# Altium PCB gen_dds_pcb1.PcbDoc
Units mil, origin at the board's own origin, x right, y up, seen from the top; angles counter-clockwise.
Board outline 6000 x 4000 mil, 2 copper layers (Top Layer, Bottom Layer); 23 components, 25 nets, 105 pads, 7 vias.
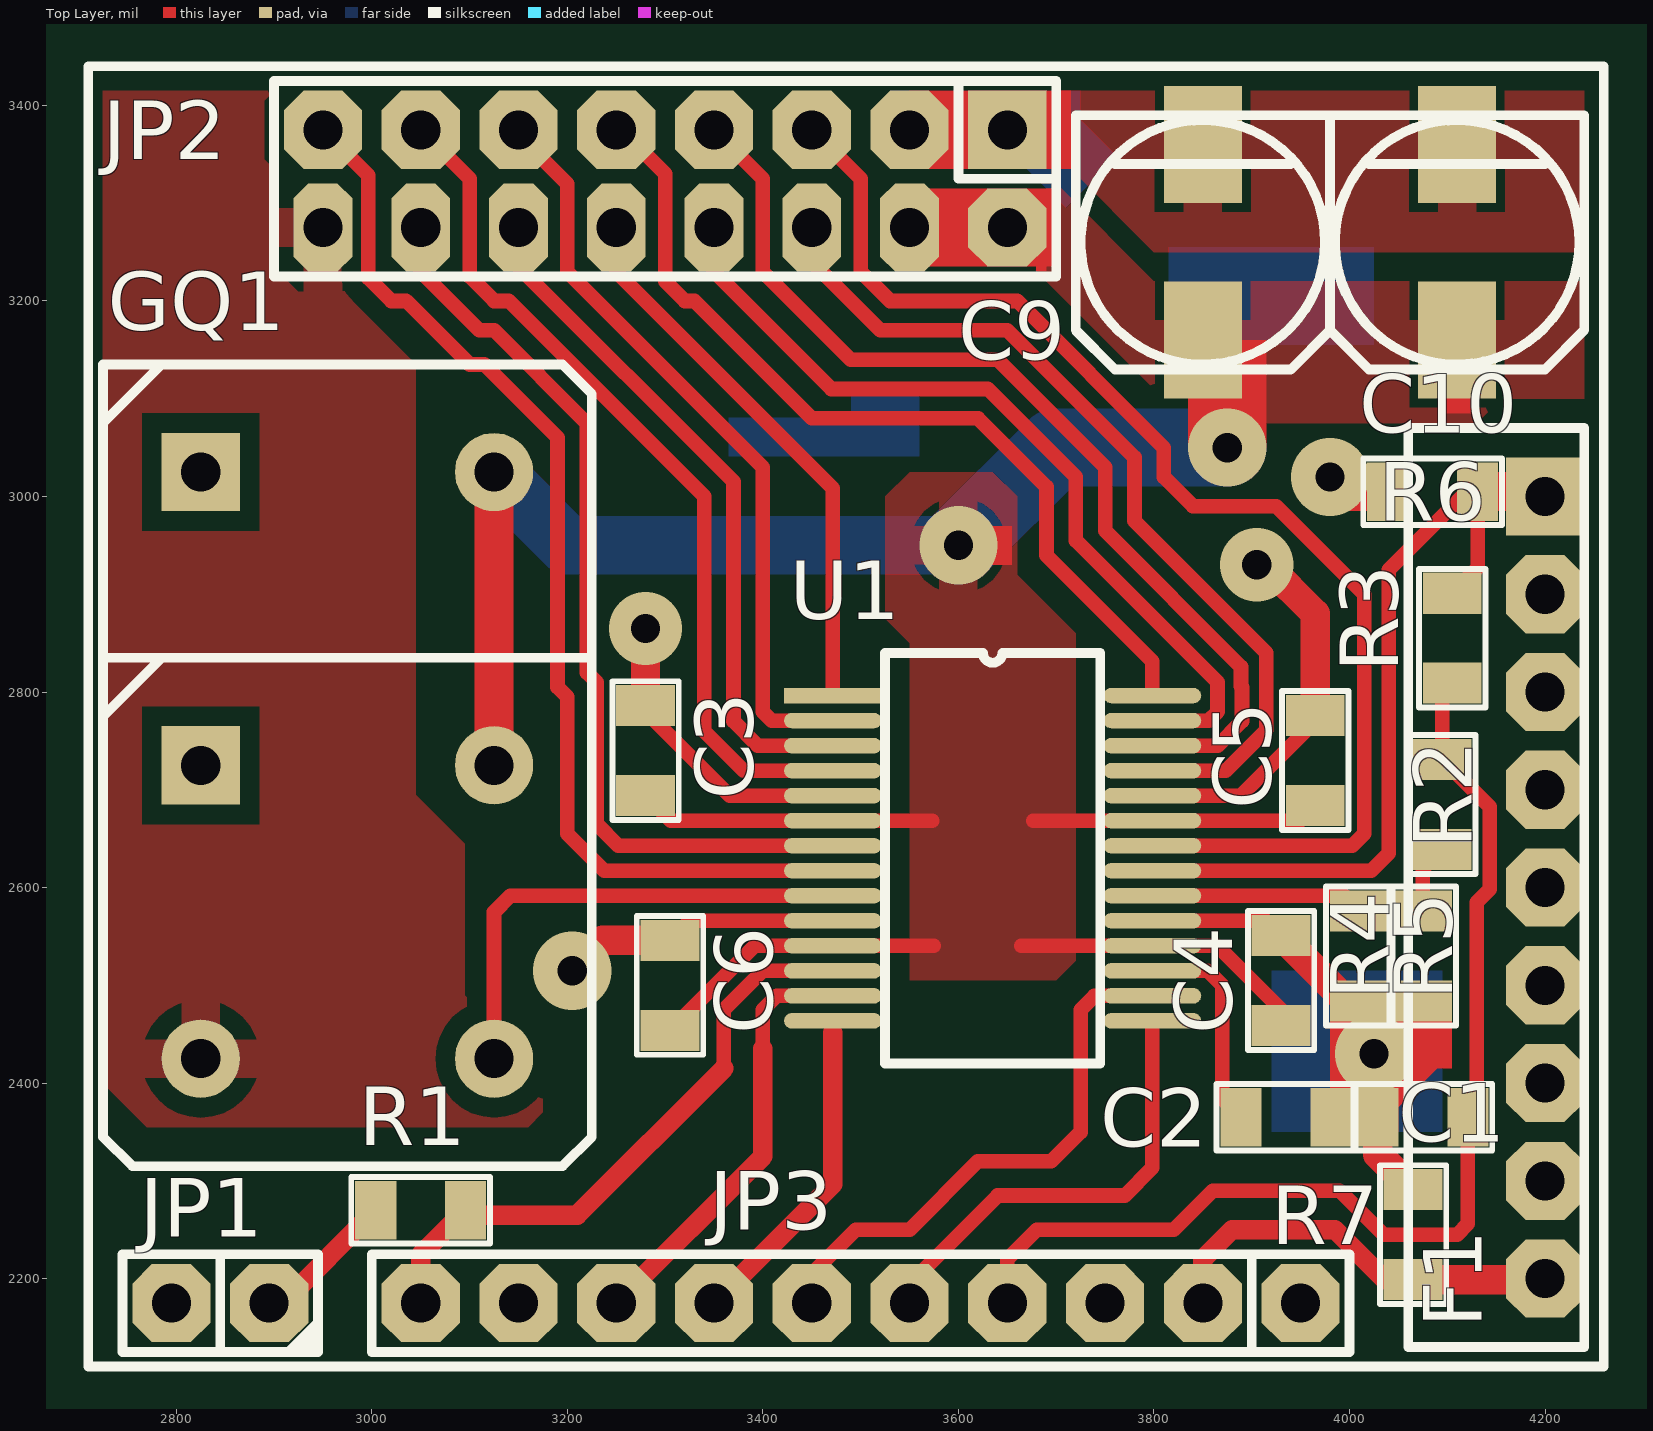
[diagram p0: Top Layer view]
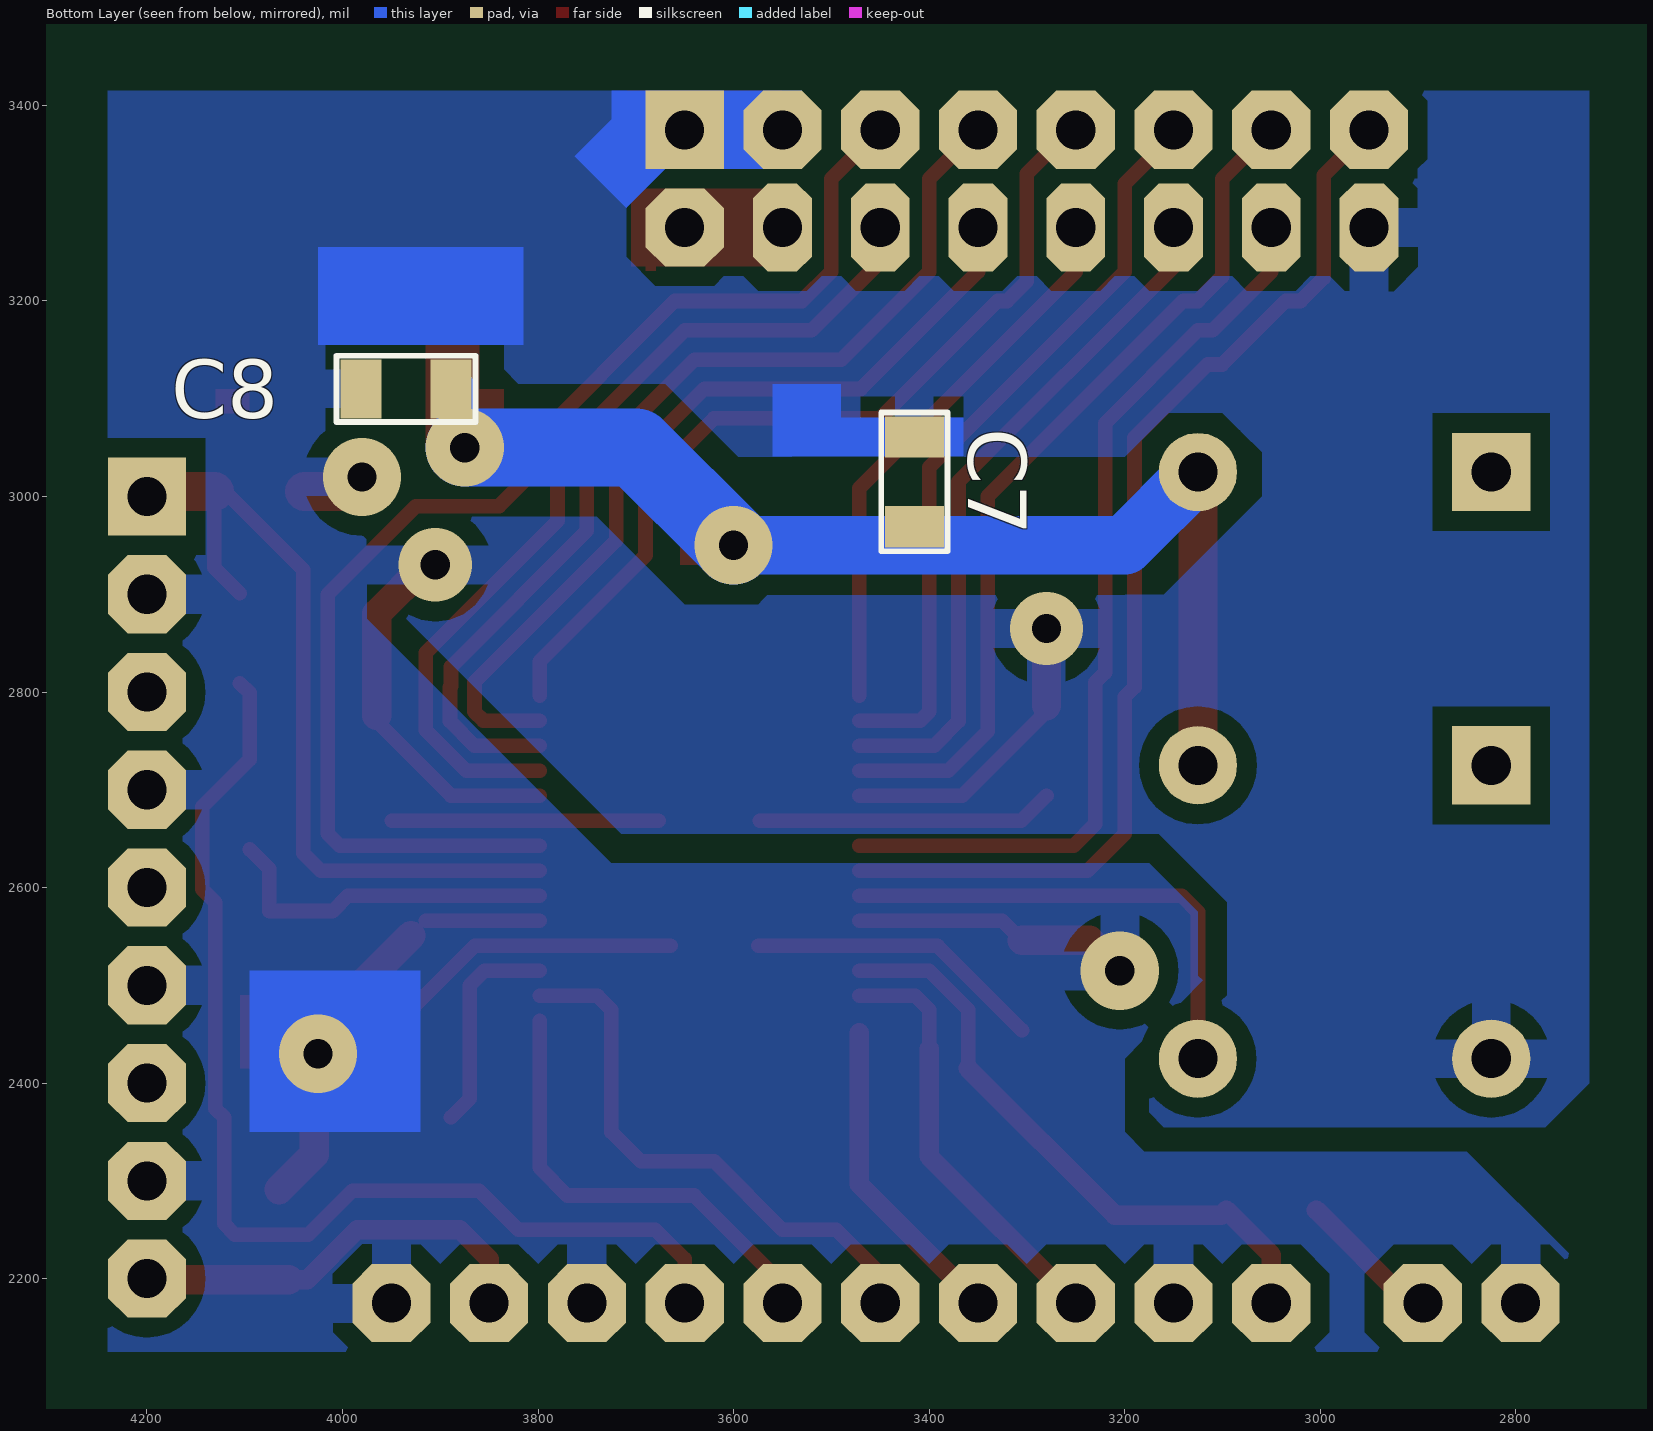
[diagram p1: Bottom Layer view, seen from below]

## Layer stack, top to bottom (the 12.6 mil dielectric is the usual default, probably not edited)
Top Layer: signal copper 1.4
Dielectric: dielectric 12.6, FR-4, Dk 4.8
Bottom Layer: signal copper 1.4

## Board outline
1000,1000 7000,1000 7000,5000 1000,5000

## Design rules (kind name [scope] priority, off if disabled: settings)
Clearance [All] p1: gap=20
PlaneConnect [All] p1: planeconnectstyle=Relief reliefexpansion=20 reliefentries=4 reliefconductorwidth=40 reliefairgap=20
PolygonConnect [All] p1: connectstyle=Relief reliefconductorwidth=40 reliefentries=4 polygonreliefangle="90 Angle"
RoutingVias [All] p1: holewidth=28 width=50 viastyle="Through Hole" minholewidth=28 minwidth=50 maxholewidth=28 maxwidth=50
SilkscreenOverComponentPads [All] p1: minsilkscreentomaskgap=10
SolderMaskExpansion [All] p1: expansion=4
Width [All] p1: maxlimit=80 minlimit=10 preferedwidth=20 minimp=50.000000 maximp=50.000000 favimp=50.000000
26 further rules are at their usual default settings.

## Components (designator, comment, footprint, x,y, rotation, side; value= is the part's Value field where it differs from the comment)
C1 "2,2n" 0805 4075,2365 r180 top
C2 "100n" 0805 3935,2365 r0 top
C3 "100n" 0805 3280,2740 r90 top
C4 "100n" 0805 3930,2505 r90 top
C5 "100n" 0805 3965,2730 r90 top
C6 "100n" 0805 3305,2500 r90 top
C7 "100n" 0805 3415,3015 r90 bottom
C8 "100n" 0805 3935,3110 r0 bottom
C9 "100u" SMD_C 3850,3260 r90 top
C10 "100u" SMD_C 4110,3260 r90 top
F1 "P7LP-606L Coilcraft" P7LP 4200,3000 r0 top
GQ1 "30MHz" GENU 2825,3025 r0 top
JP1 "G2" G2 2895,2175 r270 top
JP2 "G2*8" G2*8 3650,3375 r270 top
JP3 "G10" G10 3950,2175 r270 top
R1 "3,9k" 0805 3050,2270 r0 top
R2 "100k" 0805 4095,2685 r270 top
R3 "100k" 0805 4105,2855 r90 top
R4 "50" 0805 4010,2530 r90 top
R5 "50" 0805 4075,2530 r90 top
R6 "50" 0805 4085,3005 r0 top
R7 "50" 0805 4065,2245 r270 top
U1 "AD9851" SSOP28 3635,2630 r0 top

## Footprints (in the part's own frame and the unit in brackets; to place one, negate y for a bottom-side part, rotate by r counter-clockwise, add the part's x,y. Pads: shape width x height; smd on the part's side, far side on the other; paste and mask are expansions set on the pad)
0805 [mil]
  rect 42x60 smd: 1(-46,0) 2(46,0)
  silkscreen extent -71,-34 71,34
G2 [mil]
  oct 80x80 hole 40: 1(0,0) 2(0,-100)
  silkscreen extent -50,-150 50,50
G2*8 [mil]
  rect 80x80 hole 40: 1(0,0)
  oct 80x80 hole 40: 2(100,0) 3(0,-100) 5(0,-200) 7(0,-300) 9(0,-400) 11(0,-500) 13(0,-600) 15(0,-700)
  oct 90x60 hole 40: 4(100,-100) 6(100,-200) 8(100,-300) 10(100,-400) 12(100,-500) 14(100,-600) 16(100,-700)
  silkscreen extent -50,-750 150,50
G10 [mil]
  oct 80x80 hole 40: 1(0,0) 2(0,-100) 3(0,-200) 4(0,-300) 5(0,-400) 6(0,-500) 7(0,-600) 8(0,-700) 9(0,-800) 10(0,-900)
  silkscreen extent -50,-950 50,50
GENU [mil]
  rect 80x80 hole 40: 1(0,-300) 1(0,0)
  round 80 hole 40: 7(0,-600) 8(300,-600) 14(300,-300) 14(300,0)
  silkscreen extent -100,-710 400,110
P7LP [mil]
  rect 80x80 hole 40: 1(0,0)
  oct 80x80 hole 40: 2(0,-100) 3(0,-200) 4(0,-300) 5(0,-400) 6(0,-500) 7(0,-600) 8(0,-700) 9(0,-800)
  silkscreen extent -140,-870 40,70
SMD_C [mil]
  rect 120x80 smd: 1(-100,0) 2(100,0)
  silkscreen extent -130,-130 130,130
SSOP28 [mm]
  rect 2.54x0.4 smd: 1(-4.15,4.225)
  oval 2.54x0.4 smd: 2(-4.15,3.575) 3(-4.15,2.925) 4(-4.15,2.275) 5(-4.15,1.625) 6(-4.15,0.975) 7(-4.15,0.325) 8(-4.15,-0.325) 9(-4.15,-0.975) 10(-4.15,-1.625) 11(-4.15,-2.275) 12(-4.15,-2.925) 13(-4.15,-3.575) 14(-4.15,-4.225) 15(4.15,-4.225) 16(4.15,-3.575) 17(4.15,-2.925) 18(4.15,-2.275) 19(4.15,-1.625) 20(4.15,-0.975) 21(4.15,-0.325) 22(4.15,0.325) 23(4.15,0.975) 24(4.15,1.625) 25(4.15,2.275) 26(4.15,2.925) 27(4.15,3.575) 28(4.15,4.225)
  silkscreen extent -2.79,-5.33 2.79,5.33

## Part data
C1 C2 C3 C4 C5 C6 C7 C8: library part C
C9 C10: library part CE
F1: library part P7LP
GQ1: library part GENU
R1 R2 R3 R4 R5 R6 R7: library part R

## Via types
v1: diameter 80, hole 30, Top Layer to Bottom Layer, 5 vias
v2: diameter 75, hole 30, Top Layer to Bottom Layer, 2 vias

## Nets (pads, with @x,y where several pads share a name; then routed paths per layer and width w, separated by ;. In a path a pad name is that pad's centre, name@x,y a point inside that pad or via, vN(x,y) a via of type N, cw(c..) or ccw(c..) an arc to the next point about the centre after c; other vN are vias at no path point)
+5V: C3.1 C4.1 C5.1 C6.1 C7.1 C8.1 C9.1 C10.1 GQ1.14 JP2.2 JP2.4 U1.6 U1.11 U1.18 U1.23 | length 2360.9
  Top Layer w15: C3.1 3305.61,2668.39 U1.6 3573.39,2668.39 ; C6.1 3391.43,2540.43 U1.11 3574.57,2540.43 ; 3664.57,2540.43 U1.18 3864.57,2540.43 C4.1@3930,2475 ; 3676.61,2668.39 U1.23 C5.1@3949.39,2668.39
  Top Layer w40: GQ1.14@3125,2725 GQ1.14@3125,3025
  Bottom Layer w40: v1(3875,3050) 3884,3059 C8.1@3884,3110
  Bottom Layer w60: GQ1.14@3125,3025 3200,2950 v1(3600,2950)
  Bottom Layer w80: v1(3600,2950) 3700,3050 v1(3875,3050)
D0: JP2.13 U1.4 | length 892.3
  Top Layer w15: JP2.13 3100,3325 3100,3225 3125,3200 3140,3200 3340,3000 3340,2760 3380.43,2719.57 U1.4
D1: JP2.12 U1.3 | length 708
  Top Layer w15: JP2.12 3150,3235 3370,3015 3370,2770 3394.84,2745.16 U1.3
D2: JP2.11 U1.2 | length 774
  Top Layer w15: JP2.11 3150,3370 3200,3320 3200,3230 3400,3030 3400,2780 3409.25,2770.75 U1.2
D3: JP2.10 U1.1 | length 570.5
  Top Layer w15: JP2.10 3250,3230 3471.61,3008.39 U1.1
D4: JP2.9 U1.28 | length 914.2
  Top Layer w15: JP2.9 3255,3375 3300,3330 3300,3220 3320,3200 3330,3200 3450,3080 3620,3080 3690,3010 3690,2940 3798.39,2831.61 U1.28
D5: JP2.8 U1.27 | length 872.5
  Top Layer w15: JP2.8 3350,3230 3470,3110 3630,3110 3720,3020 3720,2955 3865,2810 3865,2780 3855.75,2770.75 U1.27
D6: JP2.7 U1.26 | length 1018.4
  Top Layer w15: JP2.7 3400,3325 3400,3230 3490,3140 3640,3140 3750,3030 3750,2965 3889,2826 3889,2806 3890,2805 3890,2770 3865.16,2745.16 U1.26
D7: JP2.6 U1.25 | length 916.5
  Top Layer w15: JP2.6 3450,3240 3520,3170 3650,3170 3780,3040 3780,2975 3915,2840 3915,2761.06 3873.51,2719.57 U1.25
FQ_UD: JP2.15 U1.8 | length 1128.4
  Top Layer w15: JP2.15 2996.5,3328.5 2996.5,3223.5 3020,3200 3035,3200 3100,3135 3115,3135 3190,3060 3190,2805 3200,2795 3200,2655 3237.8,2617.2 U1.8
GND: C1.2 C2.2 C3.2 C4.2 C5.2 C6.2 C7.2 C8.2 C9.2 C10.2 F1.2 F1.4 F1.6 F1.8 GQ1.7 JP1.2 JP2.1 JP2.3 JP2.16 JP3.1 JP3.3 JP3.9 R4.1 R5.1 R6.1 R7.1 U1.5 U1.10 U1.19 U1.24 | length 1464.3
  Top Layer w15: C3.2 3280,2780 3366.02,2693.98 U1.5 ; C6.2 3325.02,2566.02 U1.10 ; U1.19 C4.2@3914.98,2566.02 ; U1.24 3888.98,2693.98 C5.2@3965,2770
  Top Layer w30: v1(3205,2515) 3236,2546 C6.2 ; C3.2 v2(3280,2865) ; v2@3915,2930 3965,2880 C5.2 ; C4.2 3997,2484 R4.1 R5.1 ; C2.2 C1.2 4029,2327 R7.1
  Top Layer w40: v1(3980,3020) 3995,3005 R6.1
  other v1: 4025,2430
  other v2: 3905,2930
NetC1_1: C1.1 JP3.4 R2.1 R3.1 | length 1154.7
  Top Layer w15: JP3.4 3650,2220 3680,2250 3820,2250 3860,2290 3990,2290 4035,2245 4110,2245 4121,2256 C1.1 4130,2374 4130,2585 4143.5,2598.5 4143.5,2682.5 R2.1 4095,2799 R3.1
NetC2_1: C2.1 U1.17 | length 220.6
  Top Layer w15: U1.17 3855.16,2514.84 3870,2500 3870,2384 C2.1
NetF1_1: F1.1 R3.2 R6.2 U1.21 | length 849
  Top Layer w15: U1.21 4022.2,2617.2 4040,2635 4040,2925 4120,3005 R6.2 4131,2927 R3.2 ; F1.1@4195,3005 F1.1
  Top Layer w40: R6.2 F1.1@4195,3005
NetF1_9: F1.9 JP3.2 R7.2 | length 429
  Top Layer w15: F1.9@4199,2199 F1.9
  Top Layer w20: JP3.2 3850,2220 3880,2250 3985,2250 4036,2199 R7.2@4055,2199
  Top Layer w30: R7.2@4055,2199 F1.9@4199,2199
NetGQ1_8: GQ1.8 U1.9 | length 503.5
  Top Layer w15: GQ1.8 3125,2575 3141.61,2591.61 U1.9
NetJP1_1: JP1.1 R1.1 | length 148.4
  Top Layer w15: JP1.1 JP1.1@2909,2175
  Top Layer w20: JP1.1@2909,2175 R1.1
NetJP3_5: JP3.5 U1.15 | length 467.7
  Top Layer w15: JP3.5 3550,2195 3640,2285 3770,2285 3798.39,2313.39 U1.15
NetJP3_6: JP3.6 U1.16 | length 569.4
  Top Layer w15: JP3.6 3450,2205 3495,2250 3550,2250 3620,2320 3695,2320 3725,2350 3725,2475 3739.25,2489.25 U1.16
NetJP3_7: JP3.7 U1.14 | length 326.8
  Top Layer w20: JP3.7 3471.61,2296.61 3471.61,2451.38
NetJP3_8: JP3.8 U1.13 | length 439.6
  Top Layer w15: 3400,2435 3400,2475 3414.25,2489.25 U1.13
  Top Layer w20: JP3.8 3400,2325 3400,2435
NetJP3_10: JP3.10 R1.2 U1.12 | length 630.4
  Top Layer w15: R1.2 R1.2@3101,2265 ; 3360,2415 3360,2475 3399.84,2514.84 U1.12
  Top Layer w20: JP3.10 3050,2224 R1.2 ; R1.2@3101,2265 3210,2265 3360,2415
NetR2_2: R2.2 R4.2 R5.2 U1.20 | length 354.4
  Top Layer w15: U1.20 3994.39,2591.61 R4.2 R5.2 4075,2619 R2.2
RESET: JP2.5 U1.22 | length 1301.6
  Top Layer w15: JP2.5 3500,3325 3500,3230 3530,3200 3660,3200 3810,3050 3810,3020 3840,2990 3925,2990 4015,2900 4015,2655 4002.8,2642.8 U1.22
W_CLK: JP2.14 U1.7 | length 944.2
  Top Layer w15: JP2.14 3050,3230 3110,3170 3125,3170 3220,3075 3220,2820 3230,2810 3230,2665 3252.2,2642.8 U1.7
pads on no net: F1.3 F1.5 F1.7 GQ1.1

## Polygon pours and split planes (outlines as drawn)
GND on Top Layer "Top Layer-No Net" (solid, pour order 6): 3610,3415 4240,3415 4240,3275 4240,3250 3800,3250 3715,3335 3610,3335 3610,3415
+5V on Top Layer "Top Layer-No Net" (solid, pour order 8): 3630,3315 3705,3315 3800,3220 4240,3220 4240,3100 4155,3100 4125,3070 4120,3075 3900,3075 3875,3100 3810,3100 3700,3210 3675,3235 3670,3235 3630,3235 3630,3315
+5V on Top Layer "Top Layer-No Net" (solid, pour order 12): 3660,3000 3660,2920 3720,2860 3720,2525 3700,2505 3550,2505 3550,2850 3525,2875 3525,3000 3550,3025 3635,3025 3660,3000
GND on Top Layer "Top Layer-No Net" (solid, pour order 28): 2980,3320 2900,3320 2900,3415 2725,3415 2725,2400 2770,2355 3160,2355 3175,2370 3175,2410 3095,2490 3095,2585 3095,2645 3045,2695 3045,2845 3045,3135 2970,3210 2980,3200 2980,3320
GND on Bottom Layer "Top Layer-No Net" (solid, pour order 26): 3650,3415 4240,3415 4240,2125 2745,2125 2745,2225 2850,2330 3180,2330 3200,2350 3200,2425 3120,2505 3125,2510 3125,2575 3175,2625 3510,2625 3725,2625 3975,2875 3975,3085 3975,3175 3915,3235 3845,3235 3835,3225 3835,3130 3820,3115 3770,3115 3670,3115 3595,3040 3370,3040 3200,3040 3160,3080 3155,3085 3105,3085 3100,3085 3060,3045 3060,3000 3090,2970 3160,2900 3380,2900 3565,2900 3570,2895 3575,2890 3650,2890 3740,2980 3840,2980 3905,2980 3950,2935 3950,2930 3950,2890 3715,2655 3540,2655 3165,2655 3095,2585 3095,2490 3175,2410 3175,2370 3160,2355 3090,2355 2770,2355 2725,2400 2725,3415 2900,3415 2900,3325 2980,3325 2980,3225 3675,3225 3700,3250 3700,3300 3675,3325 3665,3335 3650,3335 3650,3415

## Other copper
Top Layer:
  rectangle net GND: 3550,3335 3650,3415
  rectangle net +5V: 3540,3235 3670,3315
  rectangle net GND: 3650,3335 3715,3415
  rectangle net +5V: 3645,3235 3705,3315
  rectangle net +5V: 3679.25,3230.75 3690,3245
  rectangle net GND: 3980,2350 4050,2485
  rectangle net GND: 4025,2415 4105,2490
  region net GND: 4040.5,2365.5 4090,2415 4044.04,2460.96 3994.54,2411.46
  rectangle net +5V: 3565,2930 3655,2970
  rectangle net +5V: 3835,3050 3915,3110
  rectangle net +5V: 3860,3095 3915,3160
  rectangle net +5V: 4095,3085 4130,3110
Bottom Layer:
  rectangle net GND: 3530,3335 3725,3415
  region net GND: 3710,3295 3763.03,3348.03 3713.54,3397.53 3660.5,3344.5
  rectangle net GND: 3920,2350 4095,2515
  rectangle net GND: 3815,3155 4025,3255
  rectangle net GND: 3365,3041 3510,3081
  rectangle net GND: 3490,3041 3560,3115

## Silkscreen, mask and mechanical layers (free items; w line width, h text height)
Top Overlay:
  lines w10: 2710,2110 4240,2110 4260,2110 4260,3440 2710,3440 2710,2110
Mechanical 1:
  lines w10: 2695,2095 4275,2095 4275,3455 2695,3455 2695,2095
